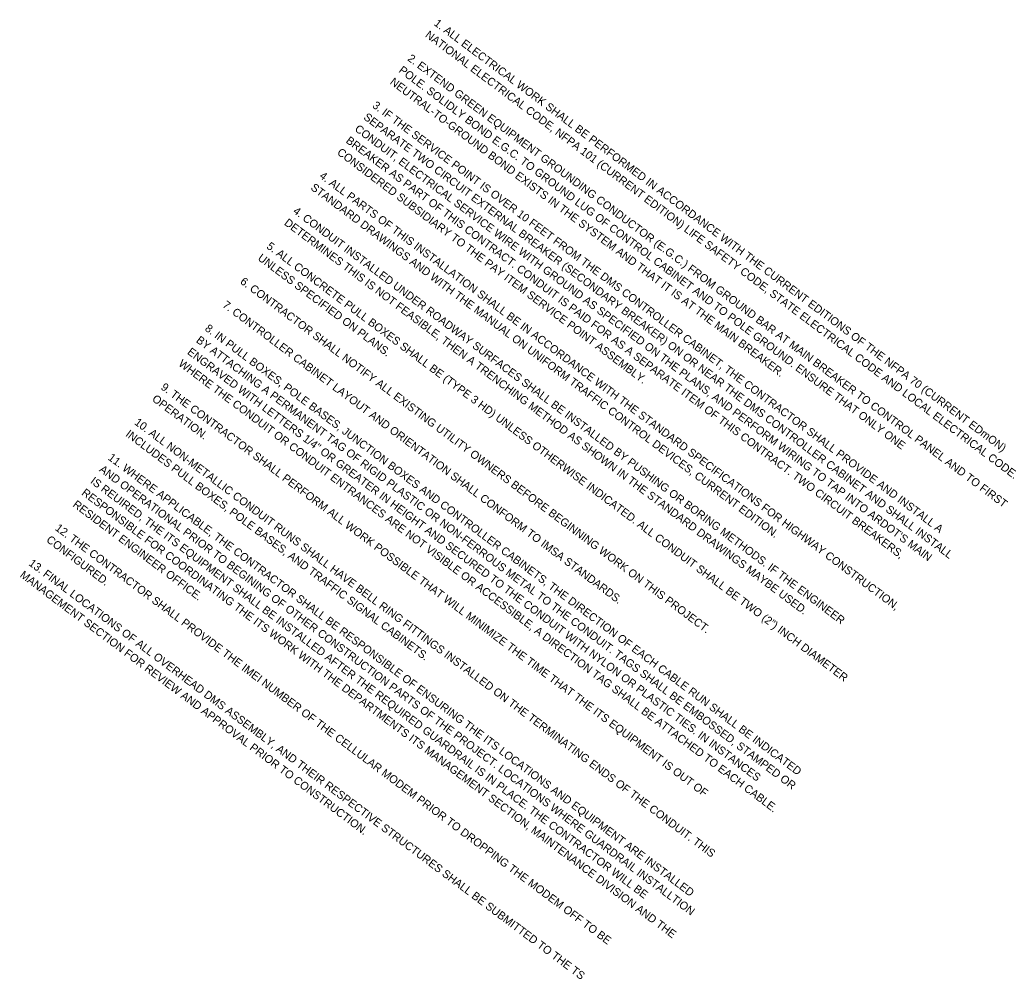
# Model space of a CAD drawing. Extents: x 626494 to 629419, y 365986 to 369334.
# Drawn here: x 626494 to 627189, y 368601 to 369269 of the extents above; entities that cross this region are included whole.
import ezdxf

# ---------------------------------------------------------------- set-up
doc = ezdxf.new("R2010")
doc.units = 0
doc.layers.add('R_Shade Frontage Road', color=7, linetype='Continuous')

msp = doc.modelspace()

# ---------------------------------------------------------------- texts
at = {"layer": 'R_Shade Frontage Road'}
for s, height, p in [('1. ALL ELECTRICAL WORK SHALL BE PERFORMED IN ACCORDANCE WITH THE CURRENT EDITIONS OF THE NFPA 70 (CURRENT EDmON) ', 5.57965, (626782.47, 369265.97)), ('NATIONAL ELECTRICAL CODE, NFPA 101 (CURRENT EDITION) LIFE SAFETY CODE, STATE ELECTRICAL CODE AND LOCAL ELECTRICAL CODE.', 5.57965, (626776.33, 369257.79)), ('2. EXTEND GREEN EQUIPMENT GROUNDING CONDUCTOR (E.G.C.) FROM GROUND BAR AT MAIN BREAKER TO CONTROL PANEL AND TO FIRST ', 5.57965, (626764.04, 369241.43)), ('POLE. SOLIDLY BOND E.G.C. TO GROUND LUG OF CONTROL CABINET AND TO POLE GROUND. ENSURE THAT ONLY ONE ', 5.5796, (626757.9, 369233.25)), ('NEUTRAL-TO-GROUND BOND EXISTS IN THE SYSTEM AND THAT IT IS AT THE MAIN BREAKER.', 5.5796, (626751.76, 369225.07)), ('3. IF THE SERVICE POINT IS OVER 10 FEET FROM THE DMS CONTROLLER CABINET, THE CONTRACTOR SHALL PROVIDE AND INSTALL A ', 5.57965, (626739.47, 369208.71)), ('SEPARATE TWO CIRCUIT EXTERNAL BREAKER (SECONDARY BREAKER) ON OR NEAR THE DMS CONTROLLER CABINET AND SHALL INSTALL ', 5.57965, (626733.33, 369200.53)), ("CONDUIT, ELECTRICAL SERVICE WIRE WITH GROUND AS SPECIFIED ON THE PLANS, AND PERFORM WIRING TO TAP INTO ARDOT'S MAIN ", 5.57965, (626727.19, 369192.35)), ('BREAKER AS PART OF THIS CONTRACT. CONDUIT IS PAID FOR AS A SEPARATE ITEM OF THIS CONTRACT. TWO CIRCUIT BREAKERS, ', 5.57965, (626721.04, 369184.17)), ('CONSIDERED SUBSIDIARY TO THE PAY ITEM SERVICE POINT ASSEMBLY. ', 5.5796, (626714.9, 369175.99)), ('4. ALL PARTS OF THIS INSTALLATION SHALL BE IN ACCORDANCE WITH THE STANDARD SPECIFICATIONS FOR HIGHWAY CONSTRUCTION, ', 5.57965, (626702.62, 369159.63)), ('STANDARD DRAWINGS AND WITH THE MANUAL ON UNIFORM TRAFFIC CONTROL DEVICES, CURRENT EDITION.', 5.5796, (626696.47, 369151.45)), ('4. CONDUIT INSTALLED UNDER ROADWAY SURFACES SHALL BE INSTALLED BY PUSHING OR BORING METHODS. IF THE ENGINEER ', 5.57965, (626684.19, 369135.09)), ('DETERMINES THIS IS NOT FEASIBLE, THEN A TRENCHING METHOD AS SHOWN IN THE STANDARD DRAWINGS MAYBE USED.', 5.57965, (626678.05, 369126.91)), ('5. ALL CONCRETE PULL BOXES SHALL BE (TYPE 3 HD) UNLESS OTHERWISE INDICATED. ALL CONDUIT SHALL BE TWO (2”) INCH DIAMETER ', 5.57965, (626665.76, 369110.55)), ('UNLESS SPECIFIED ON PLANS.', 5.5796, (626659.62, 369102.37)), ('6. CONTRACTOR SHALL NOTIFY ALL EXISTING UTILITY OWNERS BEFORE BEGINNING WORK ON THIS PROJECT. ', 5.5796, (626647.34, 369086.01)), ('7. CONTROLLER CABINET LAYOUT AND ORIENTATION SHALL CONFORM TO IMSA STANDARDS.', 5.5796, (626635.05, 369069.65)), ('8. IN PULL BOXES, POLE BASES, JUNCTION BOXES AND CONTROLLER CABINETS, THE DIRECTION OF EACH CABLE RUN SHALL BE INDICATED ', 5.57965, (626622.77, 369053.29)), ('BY ATTACHING A PERMANENT TAG OF RIGID PLASTIC OR NON-FERROUS METAL TO THE CONDUIT. TAGS SHALL BE EMBOSSED, STAMPED OR ', 5.57965, (626616.62, 369045.11)), ('ENGRAVED WITH LETTERS 1/4" OR GREATER IN HEIGHT AND SECURED TO THE CONDUIT WITH NYLON OR PLASTIC TIES. IN INSTANCES ', 5.57965, (626610.48, 369036.93)), ('WHERE THE CONDUIT OR CONDUIT ENTRANCES ARE NOT VISIBLE OR ACCESSIBLE, A DIRECTION TAG SHALL BE ATTACHED TO EACH CABLE.', 5.57965, (626604.34, 369028.75)), ('9. THE CONTRACTOR SHALL PERFORM ALL WORK POSSIBLE THAT WILL MINIMIZE THE TIME THAT THE ITS EQUIPMENT IS OUT OF ', 5.57965, (626592.05, 369012.39)), ('OPERATION.', 5.58, (626585.91, 369004.21)), ('10. ALL NON-METALLIC CONDUIT RUNS SHALL HAVE BELL RING FITTINGS INSTALLED ON THE TERMINATING ENDS OF THE CONDUIT. THIS ', 5.57965, (626573.63, 368987.85)), ('INCLUDES PULL BOXES, POLE BASES, AND TRAFFIC SIGNAL CABINETS.', 5.5796, (626567.48, 368979.67)), ('11. WHERE APPLICABLE, THE CONTRACTOR SHALL BE RESPONSIBLE OF ENSURING THE ITS LOCATIONS AND EQUIPMENT ARE INSTALLED ', 5.57965, (626555.2, 368963.31)), ('AND OPERATIONAL PRIOR TO BEGINING OF OTHER CONSTRUCTION PARTS OF THE PROJECT. LOCATIONS WHERE GUARDRAIL INSTALLTION ', 5.57965, (626549.06, 368955.13)), ('IS REUIRED, THE ITS EQUIPMENT SHALL BE INSTALLED AFTER THE REQUIRED GUARDRAIL IS IN PLACE. THE CONTRACTOR WILL BE ', 5.57965, (626542.92, 368946.95)), ('RESPONSIBLE FOR COORDINATING THE ITS WORK WITH THE DEPARTMENTS ITS MANAGEMENT SECTION, MAINTENANCE DIVISION AND THE ', 5.57965, (626536.77, 368938.77)), ('RESIDENT ENGINEER OFFICE.', 5.5796, (626530.63, 368930.59)), ('12. THE CONTRACTOR SHALL PROVIDE THE IMEI NUMBER OF THE CELLULAR MODEM PRIOR TO DROPPING THE MODEM OFF TO BE ', 5.57965, (626518.35, 368914.23)), ('CONFIGURED. ', 5.5796, (626512.2, 368906.05)), ('13. FINAL LOCATIONS OF ALL OVERHEAD DMS ASSEMBLY, AND THEIR RESPECTIVE STRUCTURES SHALL BE SUBMITTED TO THE TS ', 5.57965, (626499.92, 368889.69)), ('MANAGEMENT SECTION FOR REVIEW AND APPROVAL PRIOR TO CONSTRUCTION.', 5.5796, (626493.78, 368881.51))]:
    msp.add_text(s, height=height, rotation=323.09678, dxfattribs=at).set_placement(p)

doc.saveas('drawing.dxf')
